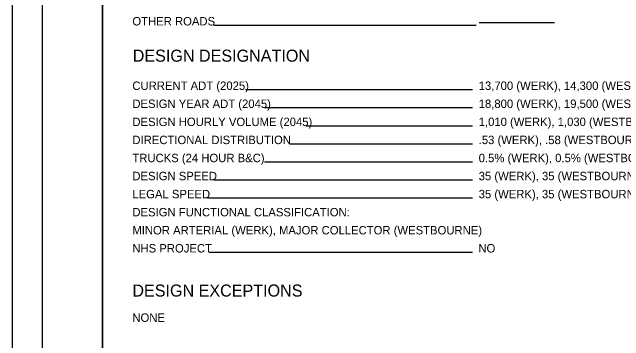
# Model space of a CAD drawing. Extents: x 0 to 34, y 0 to 22.
# Drawn here: x 0 to 10.15, y 5.64 to 11.1 of the extents above; entities that cross this region are included whole.
import ezdxf

# ---------------------------------------------------------------- set-up
doc = ezdxf.new("R2010")
doc.units = 0
for name, color, linetype in [('SH_Border', 7, 'Continuous'), ('SH_Cut_Line', 7, 'Continuous'), ('SH_Data', 7, 'Continuous'), ('SH_Text', 7, 'Continuous')]:
    doc.layers.add(name, color=color, linetype=linetype)

msp = doc.modelspace()

# ---------------------------------------------------------------- linework, layer by layer
at = {"layer": 'SH_Border'}
for points in [[(0.5, 21.5), (1.5, 21.5), (1.5, 0.5), (0.5, 0.5)], [(1.5, 21.5), (33.5, 21.5), (33.5, 0.5), (1.5, 0.5)]]:
    msp.add_lwpolyline(points, close=True, dxfattribs=at)
at = {"layer": 'SH_Cut_Line'}
msp.add_lwpolyline([(0, 0), (34, 0), (34, 22), (0, 22)], close=True, dxfattribs=at)
at = {"layer": 'SH_Data'}
for p, q in [((7.7, 10.877), (3.347, 10.877)), ((9, 10.922), (7.75, 10.922)), ((7.642, 9.806), (3.871, 9.806)), ((7.637, 9.506), (4.189, 9.506)), ((7.637, 9.206), (4.872, 9.206)), ((7.637, 8.906), (4.604, 8.906)), ((7.637, 8.606), (4.189, 8.606)), ((7.637, 8.306), (3.346, 8.306)), ((7.637, 8.006), (3.242, 8.006)), ((7.637, 7.106), (3.267, 7.106))]:
    msp.add_line(p, q, dxfattribs=at)

# ---------------------------------------------------------------- texts
msp.add_text('DESIGN DESIGNATION', height=0.2, dxfattribs=at).set_placement((2, 10.275))
at = {"layer": 'SH_Text'}
for s, height, p in [('OTHER ROADS', 0.14, (1.994, 10.877)), ('CURRENT ADT (2025)', 0.14, (1.994, 9.806)), ('13,700 (WERK), 14,300 (WESTBOURNE)', 0.14, (7.742, 9.806)), ('DESIGN YEAR ADT (2045)', 0.14, (1.994, 9.506)), ('18,800 (WERK), 19,500 (WESTBOURNE)', 0.14, (7.742, 9.506)), ('DESIGN HOURLY VOLUME (2045)', 0.14, (1.994, 9.206)), ('1,010 (WERK), 1,030 (WESTBOURNE)', 0.14, (7.742, 9.206)), ('DIRECTIONAL DISTRIBUTION', 0.14, (1.994, 8.906)), ('.53 (WERK), .58 (WESTBOURNE)', 0.14, (7.742, 8.906)), ('TRUCKS (24 HOUR B&C)', 0.14, (1.994, 8.606)), ('0.5% (WERK), 0.5% (WESTBOURNE)', 0.14, (7.742, 8.606)), ('DESIGN SPEED', 0.14, (1.994, 8.306)), ('35 (WERK), 35 (WESTBOURNE SOUTH), 30 (WESTBOURNE NORTH)', 0.14, (7.742, 8.306)), ('LEGAL SPEED', 0.14, (1.994, 8.006)), ('35 (WERK), 35 (WESTBOURNE)', 0.14, (7.742, 8.006)), ('DESIGN FUNCTIONAL CLASSIFICATION:', 0.14, (1.994, 7.706)), ('MINOR ARTERIAL (WERK), MAJOR COLLECTOR (WESTBOURNE)', 0.14, (1.994, 7.406)), ('NHS PROJECT', 0.14, (1.994, 7.106)), ('NO', 0.14, (7.737, 7.106)), ('DESIGN EXCEPTIONS', 0.2, (1.994, 6.374)), ('NONE', 0.14, (1.994, 5.954))]:
    msp.add_text(s, height=height, dxfattribs=at).set_placement(p)

doc.saveas('drawing.dxf')
